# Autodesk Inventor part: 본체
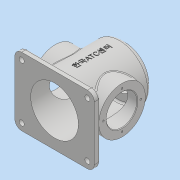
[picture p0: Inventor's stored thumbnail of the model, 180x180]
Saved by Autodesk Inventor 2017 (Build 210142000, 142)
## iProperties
Part Number: 본체
Material: 일반
Document SubType Name: Modeling
Designer: MRC
Density: 1 g/cm^3
Appearance: 기본값
Author: MRC
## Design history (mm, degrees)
sketch "스케치1"
  geometry: C1 r 50 at (0, 0); 1 further point
  constraints: 1 centre point, 1 coincident
  dimensions: "d0" = 100 diameter of C1
extrude "돌출1" new body sketch "스케치1" stored distance "d1" = 120; taper "d2" = 0 deg
sketch "스케치3"
  geometry: L1 (70, -60)-(-70, -60); L2 (-70, -60)-(-70, 60); L3 (-70, 60)-(70, 60); L4 (70, 60)-(70, -60); L5 (70, -60)-(-70, 60); L6 (-70, -60)-(70, 60); C1 r 50 at (0, 0) reference
  constraints: 12 end point, 2 midpoint, 2 parallel, 1 horizontal, 1 perpendicular
  dimensions: "d3" = 140 distance of L2.end L3.end; "d4" = 120 distance of L1.end L2.end
extrude "돌출2" join sketch "스케치3" distance "d5" = 10; taper "d6" = 0 deg
sketch "스케치4"
  geometry: C1 r 50 at (0, 0) reference; C2 r 41 at (0, 0)
  constraints: 1 centre point, 1 coincident
  dimensions: "d7" = 82 diameter of C2
extrude "돌출3" join sketch "스케치4" distance "d8" = 5; taper "d9" = 0 deg
sketch "스케치5"
  geometry: C1 r 42 at (0, 0); 1 further point
  constraints: 1 centre point, 1 coincident
  dimensions: "d10" = 84 diameter of C1
extrude "돌출4" cut sketch "스케치5" distance "d11" = 112; taper "d12" = 0 deg
sketch "스케치6"
  geometry: C1 r 41 at (0, 0) reference; C2 r 27 at (0, 0)
  constraints: 1 centre point, 1 coincident
  dimensions: "d13" = 54 diameter of C2
extrude "돌출5" cut sketch "스케치6" stored distance "d14" = 112; taper "d15" = 0 deg
node "작업 평면1"
sketch "스케치7"
  geometry: C1 r 41 at (0, 0); 1 further point
  constraints: 1 centre point, 1 coincident
  dimensions: "d17" = 82 diameter of C1
extrude "돌출6" join sketch "스케치7" stored distance "d18" = 112; taper "d19" = 0 deg
sketch "스케치8"
  geometry: C1 r 41 at (0, 0) reference; C2 r 27 at (0, 0)
  constraints: 1 centre point, 1 coincident
  dimensions: "d20" = 54 diameter of C2
extrude "돌출7" cut sketch "스케치8" stored distance "d21" = 112; taper "d22" = 0 deg
sketch "스케치9"
  geometry: C1 r 27 at (0, 0) reference; 1 further point
  constraints: 1 vertical alignment
  dimensions: "d23" = 33 distance of C1.centre point (0, 33)
hole "구멍1" sketch "스케치9" at (0, 33) diameter "d24" = 3.242; stored, may be unused: countersink angle "d28" = 90 deg, drill point angle "d30" = 118 deg; dims "d25" = 8, "d26" = 4, "d27" = 2, "d29" = 10
sketch "스케치10"
  geometry: C1 r 27 at (0, 0) reference; 1 further point
  constraints: 1 vertical alignment
  dimensions: "d34" = 33 distance of C1.centre point (0, 33)
hole "구멍2" sketch "스케치10" at (0, 33) diameter "d35" = 3.242; stored, may be unused: countersink angle "d39" = 90 deg, drill point angle "d41" = 118 deg; dims "d36" = 8, "d37" = 4, "d38" = 2, "d40" = 10
fillet "모깎기1" dims "d45" = 6
fillet "모깎기2" dims "d46" = 12
fillet "모깎기3" dims "d47" = 3
chamfer "모따기1" distance "d48" = 1; stored, may be unused: second distance "d49" = 2, angle "d50" = 45 deg
fillet "모깎기4" dims "d51" = 3
node "작업 평면2"
sketch "스케치11"
  geometry: L1 (-58, -60)-(58, -60) reference; 2 further points
  constraints: 1 vertical alignment, 1 other
  dimensions: "d52" = 66 distance from line of L1 point (0, 6)
feature "엠보싱1" sketch "스케치11" dims "d1" = 120, "d2" = 0, "d53" = 0.5, "d54" = 0
sketch "스케치12"
  geometry: C1 r 4.5 at (-58, 48); C2 r 4.5 at (58, 48); C3 r 4.5 at (58, -48); C4 r 4.5 at (-58, -48); A1 r 9 centre (58, -48) between (58, -57) and (67, -48) reference; A2 r 9 centre (58, 48) between (67, 48) and (58, 57) reference; A3 r 9 centre (-58, 48) between (-58, 57) and (-67, 48) reference; A4 r 9 centre (-58, -48) between (-67, -48) and (-58, -57) reference
  constraints: 4 centre point, 4 coincident
  dimensions: "d55" = 9 diameter of C1; "d56" = 9 diameter of C2; "d57" = 9 diameter of C3; "d58" = 9 diameter of C4
extrude "돌출8" cut sketch "스케치12" stored distance "d59" = 112; taper "d60" = 0 deg
node "솔리드1"
pattern_circular "원형 패턴1" dims angle "d32" = 360 deg
mirror "미러1"
pattern_circular "원형 패턴2" dims angle "d43" = 360 deg
other parameters: "d16" = 59
